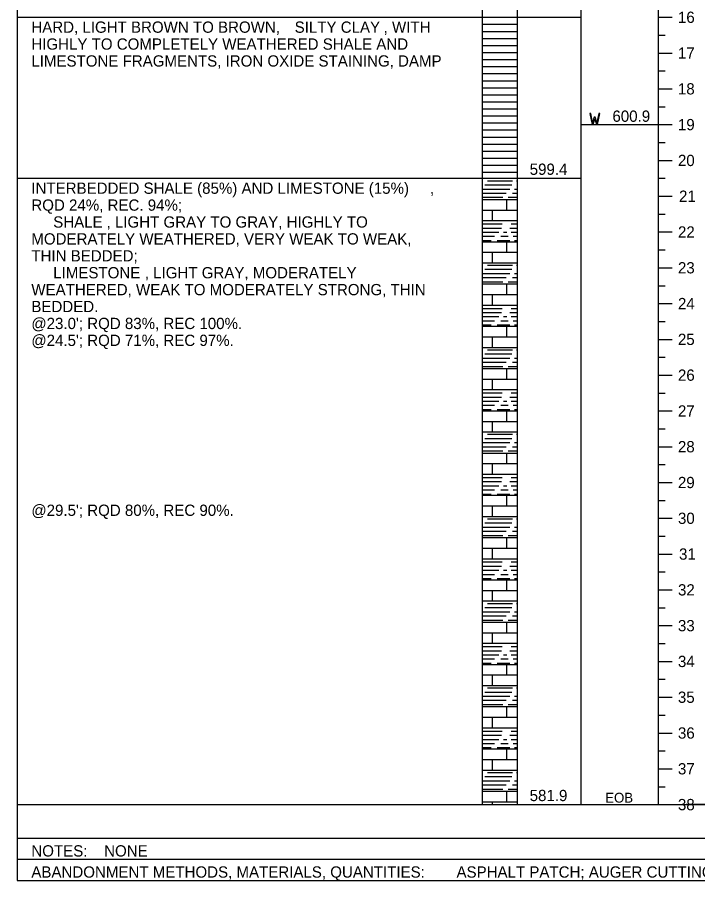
# Model space of a CAD drawing. Extents: x 0 to 0.833, y -0.32 to 0.608.
# Drawn here: x 0 to 0.403, y -0.32 to 0.19 of the extents above; entities that cross this region are included whole.
import ezdxf

# ---------------------------------------------------------------- set-up
doc = ezdxf.new("R2010")
doc.units = 0

# ---------------------------------------------------------------- blocks, each defined once
blk = doc.blocks.new('DGRFC!OHDOT FREE WATER')
blk.add_lwpolyline([(-0.00161, 0), (-0.00102, 0), (0, 0.00346), (0.00102, 0), (0.00161, 0), (0.00292, 0.00667), (0.00233, 0.00667), (0.00126, 0.00118), (0.00029, 0.00444), (-0.00029, 0.00444), (-0.00126, 0.00118), (-0.00233, 0.00667), (-0.00292, 0.00667)], close=True)

msp = doc.modelspace()

# ---------------------------------------------------------------- linework, layer by layer
msp.add_lwpolyline([(0, -0.32004), (0.83333, -0.32004), (0.83333, 0.60833), (0, 0.60833)], close=True)
for points in [[(0.29583, 0.55417), (0.29583, -0.27517)], [(0.29583, 0.55417), (0.29583, -0.27517)], [(0.33333, 0.55417), (0.33333, -0.27517)], [(0.33333, 0.55417), (0.33333, -0.27517)], [(0.275, 0.52917), (0.275, -0.27517)], [(0.37917, 0.52917), (0.37917, -0.27517)], [(0.275, 0.3175), (0.275, 0.1905)], [(0, 0.1905), (0.275, 0.1905)], [(0.275, 0.1905), (0.29583, 0.1905)], [(0.275, 0.1905), (0.29583, 0.1905)], [(0.275, 0.1905), (0.275, 0.09525)], [(0.29583, 0.1905), (0.33333, 0.1905)], [(0.37917, 0.1905), (0.3875, 0.1905)], [(0.275, 0.18633), (0.29583, 0.18633)], [(0.275, 0.18217), (0.29583, 0.18217)], [(0.37917, 0.17992), (0.38333, 0.17992)], [(0.275, 0.178), (0.29583, 0.178)], [(0.275, 0.17383), (0.29583, 0.17383)], [(0.275, 0.16967), (0.29583, 0.16967)], [(0.37917, 0.16933), (0.3875, 0.16933)], [(0.37917, 0.16933), (0.38333, 0.16933)], [(0.275, 0.1655), (0.29583, 0.1655)], [(0.275, 0.16133), (0.29583, 0.16133)], [(0.37917, 0.15875), (0.38333, 0.15875)], [(0.275, 0.15717), (0.29583, 0.15717)], [(0.275, 0.153), (0.29583, 0.153)], [(0.275, 0.14883), (0.29583, 0.14883)], [(0.37917, 0.14817), (0.3875, 0.14817)], [(0.37917, 0.14817), (0.38333, 0.14817)], [(0.275, 0.14467), (0.29583, 0.14467)], [(0.275, 0.1405), (0.29583, 0.1405)], [(0.275, 0.13633), (0.29583, 0.13633)], [(0.37917, 0.13758), (0.38333, 0.13758)], [(0.275, 0.13217), (0.29583, 0.13217)], [(0.275, 0.128), (0.29583, 0.128)], [(0.275, 0.12383), (0.29583, 0.12383)], [(0.33333, 0.127), (0.37917, 0.127)], [(0.37917, 0.127), (0.3875, 0.127)], [(0.37917, 0.127), (0.38333, 0.127)], [(0.275, 0.11967), (0.29583, 0.11967)], [(0.275, 0.1155), (0.29583, 0.1155)], [(0.37917, 0.11642), (0.38333, 0.11642)], [(0.275, 0.11133), (0.29583, 0.11133)], [(0.275, 0.10717), (0.29583, 0.10717)], [(0.275, 0.103), (0.29583, 0.103)], [(0.37917, 0.10583), (0.3875, 0.10583)], [(0.37917, 0.10583), (0.38333, 0.10583)], [(0.275, 0.09883), (0.29583, 0.09883)], [(0, 0.09525), (0.275, 0.09525)], [(0.275, 0.09525), (0.29583, 0.09525)], [(0.275, 0.09525), (0.29583, 0.09525)], [(0.275, 0.09525), (0.275, -0.27517)], [(0.27825, 0.09383), (0.293, 0.09383)], [(0.29542, 0.09383), (0.29583, 0.09383)], [(0.29583, 0.09525), (0.33333, 0.09525)], [(0.37917, 0.09525), (0.38333, 0.09525)], [(0.275, 0.08892), (0.29133, 0.08892)], [(0.27667, 0.09142), (0.29258, 0.09142)], [(0.29417, 0.08892), (0.29583, 0.08892)], [(0.275, 0.0865), (0.28933, 0.0865)], [(0.275, 0.084), (0.28725, 0.084)], [(0.275, 0.08275), (0.29583, 0.08275)], [(0.28958, 0.0765), (0.28958, 0.08275)], [(0.2905, 0.084), (0.29583, 0.084)], [(0.293, 0.0865), (0.29583, 0.0865)], [(0.37917, 0.08467), (0.3875, 0.08467)], [(0.37917, 0.08467), (0.38333, 0.08467)], [(0.275, 0.0765), (0.29583, 0.0765)], [(0.28125, 0.07025), (0.28125, 0.0765)], [(0.37917, 0.07408), (0.38333, 0.07408)], [(0.275, 0.07025), (0.29583, 0.07025)], [(0.275, 0.06833), (0.28683, 0.06833)], [(0.29217, 0.06833), (0.29583, 0.06833)], [(0.275, 0.06583), (0.28642, 0.06583)], [(0.275, 0.06342), (0.28483, 0.06342)], [(0.28767, 0.06342), (0.28967, 0.06342)], [(0.29133, 0.06583), (0.29583, 0.06583)], [(0.29217, 0.06342), (0.29583, 0.06342)], [(0.37917, 0.0635), (0.3875, 0.0635)], [(0.37917, 0.0635), (0.38333, 0.0635)], [(0.275, 0.061), (0.28233, 0.061)], [(0.275, 0.0585), (0.28033, 0.0585)], [(0.275, 0.05775), (0.29583, 0.05775)], [(0.284, 0.0585), (0.29133, 0.0585)], [(0.286, 0.061), (0.2905, 0.061)], [(0.28958, 0.0515), (0.28958, 0.05775)], [(0.29342, 0.061), (0.29583, 0.061)], [(0.29417, 0.0585), (0.29583, 0.0585)], [(0.275, 0.0515), (0.29583, 0.0515)], [(0.28125, 0.04525), (0.28125, 0.0515)], [(0.37917, 0.05292), (0.38333, 0.05292)], [(0.275, 0.04525), (0.29583, 0.04525)], [(0.27667, 0.04142), (0.29258, 0.04142)], [(0.27825, 0.04383), (0.293, 0.04383)], [(0.29542, 0.04383), (0.29583, 0.04383)], [(0.37917, 0.04233), (0.3875, 0.04233)], [(0.37917, 0.04233), (0.38333, 0.04233)], [(0.275, 0.03892), (0.29133, 0.03892)], [(0.275, 0.0365), (0.28933, 0.0365)], [(0.293, 0.0365), (0.29583, 0.0365)], [(0.29417, 0.03892), (0.29583, 0.03892)], [(0.275, 0.034), (0.28725, 0.034)], [(0.275, 0.03275), (0.29583, 0.03275)], [(0.28958, 0.0265), (0.28958, 0.03275)], [(0.2905, 0.034), (0.29583, 0.034)], [(0.37917, 0.03175), (0.38333, 0.03175)], [(0.275, 0.0265), (0.29583, 0.0265)], [(0.28125, 0.02025), (0.28125, 0.0265)], [(0.37917, 0.02117), (0.3875, 0.02117)], [(0.37917, 0.02117), (0.38333, 0.02117)], [(0.275, 0.02025), (0.29583, 0.02025)], [(0.275, 0.01833), (0.28683, 0.01833)], [(0.275, 0.01583), (0.28642, 0.01583)], [(0.29133, 0.01583), (0.29583, 0.01583)], [(0.29217, 0.01833), (0.29583, 0.01833)], [(0.275, 0.01342), (0.28483, 0.01342)], [(0.275, 0.011), (0.28233, 0.011)], [(0.286, 0.011), (0.2905, 0.011)], [(0.28767, 0.01342), (0.28967, 0.01342)], [(0.29217, 0.01342), (0.29583, 0.01342)], [(0.29342, 0.011), (0.29583, 0.011)], [(0.37917, 0.01058), (0.38333, 0.01058)], [(0.275, 0.0085), (0.28033, 0.0085)], [(0.275, 0.00775), (0.29583, 0.00775)], [(0.284, 0.0085), (0.29133, 0.0085)], [(0.28958, 0.0015), (0.28958, 0.00775)], [(0.29417, 0.0085), (0.29583, 0.0085)], [(0.275, 0.0015), (0.29583, 0.0015)], [(0.28125, -0.00475), (0.28125, 0.0015)], [(0.37917, 0), (0.3875, 0)], [(0.37917, 0), (0.38333, 0)], [(0.275, -0.00475), (0.29583, -0.00475)], [(0.27667, -0.00858), (0.29258, -0.00858)], [(0.27825, -0.00617), (0.293, -0.00617)], [(0.29542, -0.00617), (0.29583, -0.00617)], [(0.275, -0.01108), (0.29133, -0.01108)], [(0.275, -0.0135), (0.28933, -0.0135)], [(0.293, -0.0135), (0.29583, -0.0135)], [(0.29417, -0.01108), (0.29583, -0.01108)], [(0.37917, -0.01058), (0.38333, -0.01058)], [(0.275, -0.016), (0.28725, -0.016)], [(0.275, -0.01725), (0.29583, -0.01725)], [(0.28958, -0.0235), (0.28958, -0.01725)], [(0.2905, -0.016), (0.29583, -0.016)], [(0.275, -0.0235), (0.29583, -0.0235)], [(0.28125, -0.02975), (0.28125, -0.0235)], [(0.37917, -0.02117), (0.3875, -0.02117)], [(0.37917, -0.02117), (0.38333, -0.02117)], [(0.275, -0.02975), (0.29583, -0.02975)], [(0.275, -0.03167), (0.28683, -0.03167)], [(0.275, -0.03417), (0.28642, -0.03417)], [(0.29133, -0.03417), (0.29583, -0.03417)], [(0.29217, -0.03167), (0.29583, -0.03167)], [(0.37917, -0.03175), (0.38333, -0.03175)], [(0.275, -0.03658), (0.28483, -0.03658)], [(0.275, -0.039), (0.28233, -0.039)], [(0.286, -0.039), (0.2905, -0.039)], [(0.28767, -0.03658), (0.28967, -0.03658)], [(0.29217, -0.03658), (0.29583, -0.03658)], [(0.29342, -0.039), (0.29583, -0.039)], [(0.275, -0.0415), (0.28033, -0.0415)], [(0.275, -0.04225), (0.29583, -0.04225)], [(0.284, -0.0415), (0.29133, -0.0415)], [(0.28958, -0.0485), (0.28958, -0.04225)], [(0.29417, -0.0415), (0.29583, -0.0415)], [(0.37917, -0.04233), (0.3875, -0.04233)], [(0.37917, -0.04233), (0.38333, -0.04233)], [(0.275, -0.0485), (0.29583, -0.0485)], [(0.28125, -0.05475), (0.28125, -0.0485)], [(0.275, -0.05475), (0.29583, -0.05475)], [(0.27825, -0.05617), (0.293, -0.05617)], [(0.29542, -0.05617), (0.29583, -0.05617)], [(0.37917, -0.05292), (0.38333, -0.05292)], [(0.275, -0.06108), (0.29133, -0.06108)], [(0.27667, -0.05858), (0.29258, -0.05858)], [(0.29417, -0.06108), (0.29583, -0.06108)], [(0.275, -0.0635), (0.28933, -0.0635)], [(0.275, -0.066), (0.28725, -0.066)], [(0.2905, -0.066), (0.29583, -0.066)], [(0.293, -0.0635), (0.29583, -0.0635)], [(0.37917, -0.0635), (0.3875, -0.0635)], [(0.37917, -0.0635), (0.38333, -0.0635)], [(0.275, -0.06725), (0.29583, -0.06725)], [(0.28958, -0.0735), (0.28958, -0.06725)], [(0.275, -0.0735), (0.29583, -0.0735)], [(0.28125, -0.07975), (0.28125, -0.0735)], [(0.37917, -0.07408), (0.38333, -0.07408)], [(0.275, -0.07975), (0.29583, -0.07975)], [(0.275, -0.08167), (0.28683, -0.08167)], [(0.29217, -0.08167), (0.29583, -0.08167)], [(0.275, -0.08417), (0.28642, -0.08417)], [(0.275, -0.08658), (0.28483, -0.08658)], [(0.28767, -0.08658), (0.28967, -0.08658)], [(0.29133, -0.08417), (0.29583, -0.08417)], [(0.29217, -0.08658), (0.29583, -0.08658)], [(0.37917, -0.08467), (0.3875, -0.08467)], [(0.37917, -0.08467), (0.38333, -0.08467)], [(0.275, -0.089), (0.28233, -0.089)], [(0.275, -0.0915), (0.28033, -0.0915)], [(0.284, -0.0915), (0.29133, -0.0915)], [(0.286, -0.089), (0.2905, -0.089)], [(0.29342, -0.089), (0.29583, -0.089)], [(0.29417, -0.0915), (0.29583, -0.0915)], [(0.275, -0.09225), (0.29583, -0.09225)], [(0.28958, -0.0985), (0.28958, -0.09225)], [(0.37917, -0.09525), (0.38333, -0.09525)], [(0.275, -0.0985), (0.29583, -0.0985)], [(0.28125, -0.10475), (0.28125, -0.0985)], [(0.275, -0.10475), (0.29583, -0.10475)], [(0.27825, -0.10617), (0.293, -0.10617)], [(0.29542, -0.10617), (0.29583, -0.10617)], [(0.37917, -0.10583), (0.3875, -0.10583)], [(0.37917, -0.10583), (0.38333, -0.10583)], [(0.275, -0.11108), (0.29133, -0.11108)], [(0.27667, -0.10858), (0.29258, -0.10858)], [(0.29417, -0.11108), (0.29583, -0.11108)], [(0.275, -0.1135), (0.28933, -0.1135)], [(0.275, -0.116), (0.28725, -0.116)], [(0.275, -0.11725), (0.29583, -0.11725)], [(0.28958, -0.1235), (0.28958, -0.11725)], [(0.2905, -0.116), (0.29583, -0.116)], [(0.293, -0.1135), (0.29583, -0.1135)], [(0.37917, -0.11642), (0.38333, -0.11642)], [(0.275, -0.1235), (0.29583, -0.1235)], [(0.28125, -0.12975), (0.28125, -0.1235)], [(0.37917, -0.127), (0.3875, -0.127)], [(0.37917, -0.127), (0.38333, -0.127)], [(0.275, -0.12975), (0.29583, -0.12975)], [(0.275, -0.13167), (0.28683, -0.13167)], [(0.29217, -0.13167), (0.29583, -0.13167)], [(0.275, -0.13417), (0.28642, -0.13417)], [(0.275, -0.13658), (0.28483, -0.13658)], [(0.28767, -0.13658), (0.28967, -0.13658)], [(0.29133, -0.13417), (0.29583, -0.13417)], [(0.29217, -0.13658), (0.29583, -0.13658)], [(0.37917, -0.13758), (0.38333, -0.13758)], [(0.275, -0.139), (0.28233, -0.139)], [(0.275, -0.1415), (0.28033, -0.1415)], [(0.275, -0.14225), (0.29583, -0.14225)], [(0.284, -0.1415), (0.29133, -0.1415)], [(0.286, -0.139), (0.2905, -0.139)], [(0.28958, -0.1485), (0.28958, -0.14225)], [(0.29342, -0.139), (0.29583, -0.139)], [(0.29417, -0.1415), (0.29583, -0.1415)], [(0.275, -0.1485), (0.29583, -0.1485)], [(0.28125, -0.15475), (0.28125, -0.1485)], [(0.37917, -0.14817), (0.3875, -0.14817)], [(0.37917, -0.14817), (0.38333, -0.14817)], [(0.275, -0.15475), (0.29583, -0.15475)], [(0.27825, -0.15617), (0.293, -0.15617)], [(0.29542, -0.15617), (0.29583, -0.15617)], [(0.275, -0.16108), (0.29133, -0.16108)], [(0.27667, -0.15858), (0.29258, -0.15858)], [(0.29417, -0.16108), (0.29583, -0.16108)], [(0.37917, -0.15875), (0.38333, -0.15875)], [(0.275, -0.1635), (0.28933, -0.1635)], [(0.275, -0.166), (0.28725, -0.166)], [(0.275, -0.16725), (0.29583, -0.16725)], [(0.28958, -0.1735), (0.28958, -0.16725)], [(0.2905, -0.166), (0.29583, -0.166)], [(0.293, -0.1635), (0.29583, -0.1635)], [(0.275, -0.1735), (0.29583, -0.1735)], [(0.28125, -0.17975), (0.28125, -0.1735)], [(0.37917, -0.16933), (0.3875, -0.16933)], [(0.37917, -0.16933), (0.38333, -0.16933)], [(0.275, -0.17975), (0.29583, -0.17975)], [(0.275, -0.18167), (0.28683, -0.18167)], [(0.29217, -0.18167), (0.29583, -0.18167)], [(0.37917, -0.17992), (0.38333, -0.17992)], [(0.275, -0.18417), (0.28642, -0.18417)], [(0.275, -0.18658), (0.28483, -0.18658)], [(0.28767, -0.18658), (0.28967, -0.18658)], [(0.29133, -0.18417), (0.29583, -0.18417)], [(0.29217, -0.18658), (0.29583, -0.18658)], [(0.275, -0.189), (0.28233, -0.189)], [(0.275, -0.1915), (0.28033, -0.1915)], [(0.275, -0.19225), (0.29583, -0.19225)], [(0.284, -0.1915), (0.29133, -0.1915)], [(0.286, -0.189), (0.2905, -0.189)], [(0.28958, -0.1985), (0.28958, -0.19225)], [(0.29342, -0.189), (0.29583, -0.189)], [(0.29417, -0.1915), (0.29583, -0.1915)], [(0.37917, -0.1905), (0.3875, -0.1905)], [(0.37917, -0.1905), (0.38333, -0.1905)], [(0.275, -0.1985), (0.29583, -0.1985)], [(0.28125, -0.20475), (0.28125, -0.1985)], [(0.37917, -0.20108), (0.38333, -0.20108)], [(0, -0.20754), (0, -0.32004), (0.83333, -0.32004), (0.83333, -0.20754)], [(0.275, -0.20475), (0.29583, -0.20475)], [(0.27667, -0.20858), (0.29258, -0.20858)], [(0.27825, -0.20617), (0.293, -0.20617)], [(0.29542, -0.20617), (0.29583, -0.20617)], [(0.275, -0.21108), (0.29133, -0.21108)], [(0.275, -0.2135), (0.28933, -0.2135)], [(0.293, -0.2135), (0.29583, -0.2135)], [(0.29417, -0.21108), (0.29583, -0.21108)], [(0.37917, -0.21167), (0.3875, -0.21167)], [(0.37917, -0.21167), (0.38333, -0.21167)], [(0.275, -0.216), (0.28725, -0.216)], [(0.275, -0.21725), (0.29583, -0.21725)], [(0.28958, -0.2235), (0.28958, -0.21725)], [(0.2905, -0.216), (0.29583, -0.216)], [(0.275, -0.2235), (0.29583, -0.2235)], [(0.28125, -0.22975), (0.28125, -0.2235)], [(0.37917, -0.22225), (0.38333, -0.22225)], [(0.275, -0.22975), (0.29583, -0.22975)], [(0.275, -0.23167), (0.28683, -0.23167)], [(0.275, -0.23417), (0.28642, -0.23417)], [(0.29133, -0.23417), (0.29583, -0.23417)], [(0.29217, -0.23167), (0.29583, -0.23167)], [(0.37917, -0.23283), (0.3875, -0.23283)], [(0.37917, -0.23283), (0.38333, -0.23283)], [(0.275, -0.23658), (0.28483, -0.23658)], [(0.275, -0.239), (0.28233, -0.239)], [(0.286, -0.239), (0.2905, -0.239)], [(0.28767, -0.23658), (0.28967, -0.23658)], [(0.29217, -0.23658), (0.29583, -0.23658)], [(0.29342, -0.239), (0.29583, -0.239)], [(0.275, -0.2415), (0.28033, -0.2415)], [(0.275, -0.24225), (0.29583, -0.24225)], [(0.284, -0.2415), (0.29133, -0.2415)], [(0.28958, -0.2485), (0.28958, -0.24225)], [(0.29417, -0.2415), (0.29583, -0.2415)], [(0.37917, -0.24342), (0.38333, -0.24342)], [(0.275, -0.2485), (0.29583, -0.2485)], [(0.28125, -0.25475), (0.28125, -0.2485)], [(0.275, -0.25475), (0.29583, -0.25475)], [(0.37917, -0.254), (0.3875, -0.254)], [(0.37917, -0.254), (0.38333, -0.254)], [(0.27667, -0.25858), (0.29258, -0.25858)], [(0.27825, -0.25617), (0.293, -0.25617)], [(0.29542, -0.25617), (0.29583, -0.25617)], [(0.275, -0.26108), (0.29133, -0.26108)], [(0.275, -0.2635), (0.28933, -0.2635)], [(0.293, -0.2635), (0.29583, -0.2635)], [(0.29417, -0.26108), (0.29583, -0.26108)], [(0.37917, -0.26458), (0.38333, -0.26458)], [(0.275, -0.266), (0.28725, -0.266)], [(0.275, -0.26725), (0.29583, -0.26725)], [(0.28958, -0.2735), (0.28958, -0.26725)], [(0.2905, -0.266), (0.29583, -0.266)], [(0, -0.27517), (0.275, -0.27517)], [(0.275, -0.2735), (0.29583, -0.2735)], [(0.275, -0.27517), (0.29583, -0.27517)], [(0.275, -0.27517), (0.29583, -0.27517)], [(0.28125, -0.27517), (0.28125, -0.2735)], [(0.29583, -0.27517), (0.33333, -0.27517)], [(0.33333, -0.27517), (0.37917, -0.27517)], [(0.37917, -0.27517), (0.4125, -0.27517)], [(0.37917, -0.27517), (0.3875, -0.27517)], [(0.37917, -0.27517), (0.38333, -0.27517)], [(0.37917, -0.27517), (0.39583, -0.27517)], [(0.4125, -0.27517), (0.39583, -0.27517)], [(0, -0.29504), (0.83333, -0.29504)], [(0, -0.30754), (0.83333, -0.30754)]]:
    msp.add_lwpolyline(points)

# ---------------------------------------------------------------- block references
msp.add_blockref('DGRFC!OHDOT FREE WATER', (0.34167, 0.127))

# ---------------------------------------------------------------- texts
for s, height, p in [('16', 0.006667, (0.39087, 0.18717)), ('HARD, LIGHT BROWN TO BROWN, ', 0.0066667, (0.00833, 0.18133)), ('SILTY CLAY', 0.006667, (0.16411, 0.18133)), (', WITH', 0.006667, (0.21674, 0.18133)), ('HIGHLY TO COMPLETELY WEATHERED SHALE AND', 0.0066667, (0.00833, 0.17133)), ('17', 0.006667, (0.39087, 0.166)), ('LIMESTONE FRAGMENTS, IRON OXIDE STAINING, DAMP', 0.0066667, (0.00833, 0.16133)), ('18', 0.006667, (0.39086, 0.14483)), ('600.9', 0.006667, (0.35211, 0.12867)), ('19', 0.006667, (0.39086, 0.12367)), ('20', 0.006667, (0.39088, 0.1025)), ('599.4', 0.006667, (0.30316, 0.09729)), ('INTERBEDDED SHALE (85%) AND LIMESTONE (15%)', 0.0066667, (0.00833, 0.08608)), (',', 0.00667, (0.24416, 0.08608)), ('21', 0.006667, (0.39151, 0.08133)), ('RQD 24%, REC. 94%;', 0.0066667, (0.00833, 0.07608)), ('SHALE', 0.006667, (0.02127, 0.06608)), (', LIGHT GRAY TO GRAY, HIGHLY TO', 0.0066667, (0.05284, 0.06608)), ('22', 0.006667, (0.3909, 0.06017)), ('MODERATELY WEATHERED, VERY WEAK TO WEAK,', 0.0066667, (0.00833, 0.05608)), ('THIN BEDDED;', 0.0066667, (0.00833, 0.04608)), ('LIMESTONE', 0.006667, (0.02127, 0.03608)), (', LIGHT GRAY, MODERATELY', 0.0066667, (0.07544, 0.03608)), ('23', 0.006667, (0.39087, 0.039)), ('WEATHERED, WEAK TO MODERATELY STRONG, THIN', 0.0066667, (0.00833, 0.02608)), ('BEDDED.', 0.006667, (0.00833, 0.01608)), ('24', 0.006667, (0.39088, 0.01783)), ("@23.0'; RQD 83%, REC 100%.", 0.0066667, (0.00833, 0.00608)), ("@24.5'; RQD 71%, REC 97%.", 0.0066667, (0.00833, -0.00392)), ('25', 0.006667, (0.39084, -0.00333)), ('26', 0.006667, (0.39087, -0.0245)), ('27', 0.006667, (0.39087, -0.04567)), ('28', 0.006667, (0.39086, -0.06683)), ('29', 0.006667, (0.39086, -0.088)), ("@29.5'; RQD 80%, REC 90%.", 0.0066667, (0.00833, -0.10442)), ('30', 0.006667, (0.39088, -0.10917)), ('31', 0.006667, (0.39151, -0.13033)), ('32', 0.006667, (0.3909, -0.1515)), ('33', 0.006667, (0.39087, -0.17267)), ('34', 0.006667, (0.39088, -0.19383)), ('35', 0.006667, (0.39084, -0.215)), ('36', 0.006667, (0.39087, -0.23617)), ('37', 0.006667, (0.39087, -0.25733)), ('581.9', 0.006667, (0.30314, -0.27312)), ('EOB', 0.005833, (0.34786, -0.27401)), ('38', 0.006667, (0.39086, -0.2785)), ('NOTES:', 0.006667, (0.00833, -0.30588)), ('NONE', 0.006667, (0.05139, -0.30588)), ('ABANDONMENT METHODS, MATERIALS, QUANTITIES:', 0.0066667, (0.00833, -0.31838)), ('ASPHALT PATCH; AUGER CUTTINGS MIXED WITH   BENTONITE CHIPS', 0.0066667, (0.25986, -0.31838))]:
    msp.add_text(s, height=height).set_placement(p)

doc.saveas('drawing.dxf')
